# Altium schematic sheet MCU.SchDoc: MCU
size A4; Date: Not used; ApprovedBy: Not used; CheckedBy: Not used; Author: Not used; CompanyName: STMicroelectronics; DrawnBy: Not used; Engineer: Not used; Organization: Not used; Address1: Not used; Address2: Not used; Address3: Not used; Address4: Not used; DocumentNumber: Not used; Revision: Not used; SheetNumber: 3; SheetTotal: 6
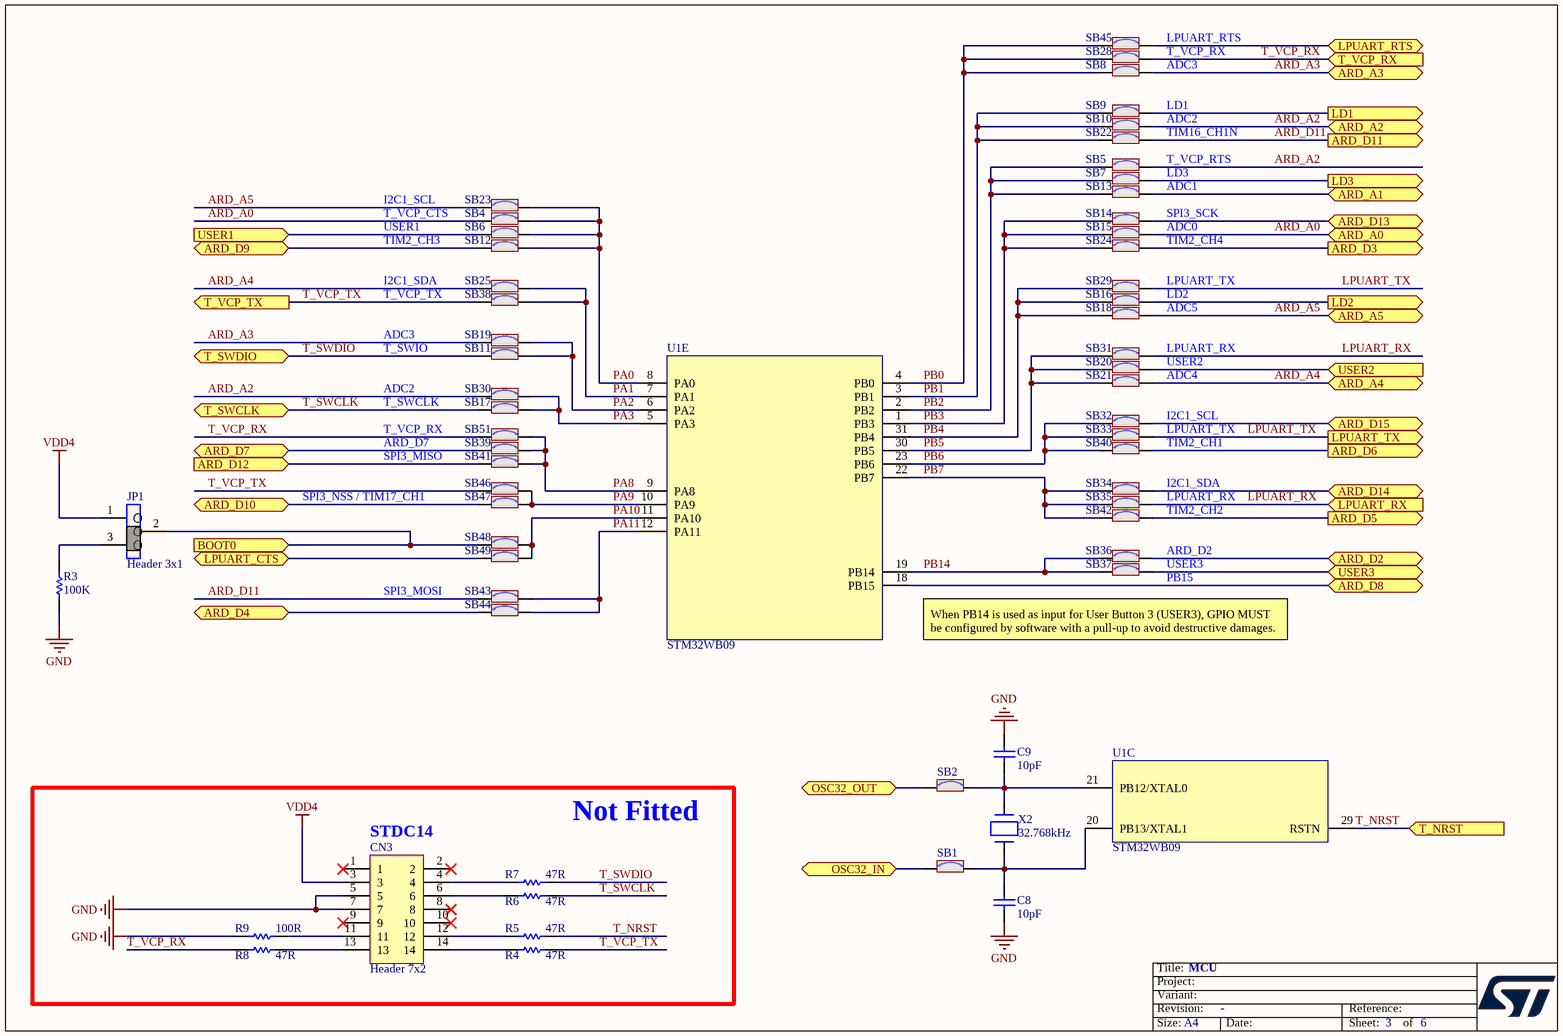
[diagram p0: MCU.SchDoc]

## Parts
C8  value 10pF  [C0402]  (hidden comment: Capacitor)
C9  value 10pF  [C0402]  (hidden comment: Capacitor)
CN3  Header 7x2  [CON_SAMTEC_FTSH-107-01-L-DV-K]
JP1  value Header 3x1  [CON_SAMTEC_TSW-103-07-F-S]  (hidden comment: Jumper_Header 3x1 Fitted 2-3)
R3  value 100K  [R0402]  (hidden comment: Resistor)
R4  value 47R  [R0402]  (hidden comment: Resistor)
R5  value 47R  [R0402]  (hidden comment: Resistor)
R6  value 47R  [R0402]  (hidden comment: Resistor)
R7  value 47R  [R0402]  (hidden comment: Resistor)
R8  value 47R  [R0402]  (hidden comment: Resistor)
R9  value 100R  [R0402]  (hidden comment: Resistor)
SB1  SB_ON  [SOLDER-BRIDGE_R0402-0R]  (value not drawn)
SB2  SB_ON  [SOLDER-BRIDGE_R0402-0R]  (value not drawn)
SB4  SB_ON  [SOLDER-BRIDGE_R0402-0R]  (value not drawn)
SB5  SB_ON  [SOLDER-BRIDGE_R0402-0R]  (value not drawn)
SB6  SB_ON  [SOLDER-BRIDGE_R0402-0R]  (value not drawn)
SB7  SB_ON  [SOLDER-BRIDGE_R0402-0R]  (value not drawn)
SB8  SB_ON  [SOLDER-BRIDGE_R0402-0R]  (value not drawn)
SB9  SB_ON  [SOLDER-BRIDGE_R0402-0R]  (value not drawn)
SB10  SB_ON  [SOLDER-BRIDGE_R0402-0R]  (value not drawn)
SB11  SB_ON  [SOLDER-BRIDGE_R0402-0R]  (value not drawn)
SB12  SB_ON  [SOLDER-BRIDGE_R0402-0R]  (value not drawn)
SB13  SB_ON  [SOLDER-BRIDGE_R0402-0R]  (value not drawn)
SB14  SB_ON  [SOLDER-BRIDGE_R0402-0R]  (value not drawn)
SB15  SB_ON  [SOLDER-BRIDGE_R0402-0R]  (value not drawn)
SB16  SB_ON  [SOLDER-BRIDGE_R0402-0R]  (value not drawn)
SB17  SB_ON  [SOLDER-BRIDGE_R0402-0R]  (value not drawn)
SB18  SB_ON  [SOLDER-BRIDGE_R0402-0R]  (value not drawn)
SB19  SB_ON  [SOLDER-BRIDGE_R0402-0R]  (value not drawn)
SB20  SB_ON  [SOLDER-BRIDGE_R0402-0R]  (value not drawn)
SB21  SB_ON  [SOLDER-BRIDGE_R0402-0R]  (value not drawn)
SB22  SB_ON  [SOLDER-BRIDGE_R0402-0R]  (value not drawn)
SB23  SB_ON  [SOLDER-BRIDGE_R0402-0R]  (value not drawn)
SB24  SB_ON  [SOLDER-BRIDGE_R0402-0R]  (value not drawn)
SB25  SB_ON  [SOLDER-BRIDGE_R0402-0R]  (value not drawn)
SB28  SB_ON  [SOLDER-BRIDGE_R0402-0R]  (value not drawn)
SB29  SB_ON  [SOLDER-BRIDGE_R0402-0R]  (value not drawn)
SB30  SB_ON  [SOLDER-BRIDGE_R0402-0R]  (value not drawn)
SB31  SB_ON  [SOLDER-BRIDGE_R0402-0R]  (value not drawn)
SB32  SB_ON  [SOLDER-BRIDGE_R0402-0R]  (value not drawn)
SB33  SB_ON  [SOLDER-BRIDGE_R0402-0R]  (value not drawn)
SB34  SB_ON  [SOLDER-BRIDGE_R0402-0R]  (value not drawn)
SB35  SB_ON  [SOLDER-BRIDGE_R0402-0R]  (value not drawn)
SB36  SB_ON  [SOLDER-BRIDGE_R0402-0R]  (value not drawn)
SB37  SB_ON  [SOLDER-BRIDGE_R0402-0R]  (value not drawn)
SB38  SB_ON  [SOLDER-BRIDGE_R0402-0R]  (value not drawn)
SB39  SB_ON  [SOLDER-BRIDGE_R0402-0R]  (value not drawn)
SB40  SB_ON  [SOLDER-BRIDGE_R0402-0R]  (value not drawn)
SB41  SB_ON  [SOLDER-BRIDGE_R0402-0R]  (value not drawn)
SB42  SB_ON  [SOLDER-BRIDGE_R0402-0R]  (value not drawn)
SB43  SB_ON  [SOLDER-BRIDGE_R0402-0R]  (value not drawn)
SB44  SB_ON  [SOLDER-BRIDGE_R0402-0R]  (value not drawn)
SB45  SB_ON  [SOLDER-BRIDGE_R0402-0R]  (value not drawn)
SB46  SB_ON  [SOLDER-BRIDGE_R0402-0R]  (value not drawn)
SB47  SB_ON  [SOLDER-BRIDGE_R0402-0R]  (value not drawn)
SB48  SB_ON  [SOLDER-BRIDGE_R0402-0R]  (value not drawn)
SB49  SB_ON  [SOLDER-BRIDGE_R0402-0R]  (value not drawn)
SB51  SB_ON  [SOLDER-BRIDGE_R0402-0R]  (value not drawn)
U1  STM32WB09  [ICC_QFN32-EPAD_5X5_P050]  (parts C,E of 5)
X2  value 32.768kHz  [CRY_NX2012SA_2P]  (hidden comment: XTAL_2_PINS)

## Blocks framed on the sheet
Not Fitted: CN3 R4-R9

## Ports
ARD_A0 (bidir), ARD_A1 (bidir), ARD_A2 (bidir), ARD_A3 (bidir), ARD_A4 (bidir), ARD_A5 (bidir), ARD_D2 (bidir), ARD_D3 (out), ARD_D4 (bidir), ARD_D5 (out), ARD_D6 (out), ARD_D7 (bidir), ARD_D8 (bidir), ARD_D9 (bidir), ARD_D10 (bidir), ARD_D11 (out), ARD_D12 (in), ARD_D13 (bidir), ARD_D14 (bidir), ARD_D15 (bidir), BOOT0 (in), LD1 (out), LD2 (out), LD3 (out), LPUART_CTS (bidir), LPUART_RTS (bidir), LPUART_RX (in), LPUART_TX (out), OSC32_IN (bidir), OSC32_OUT (bidir), T_NRST (in), T_SWCLK (bidir), T_SWDIO (bidir), T_VCP_RX (in), T_VCP_TX (out), USER1 (in), USER2 (in), USER3 (bidir)

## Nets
GND: C8.1 C9.2 CN3.5 CN3.7 R3.1 R9.1
VDD4: CN3.3 JP1.1
ARD_A0: SB4.1 SB15.2 ; port ARD_A0
ARD_A1: SB13.2 ; port ARD_A1
ARD_A2: SB5.2 SB10.2 SB30.1 ; port ARD_A2
ARD_A3: SB8.2 SB19.1 ; port ARD_A3
ARD_A4: SB21.2 SB25.1 ; port ARD_A4
ARD_A5: SB18.2 SB23.1 ; port ARD_A5
ARD_D2: SB36.2 ; port ARD_D2
ARD_D3: SB24.2 ; port ARD_D3
ARD_D4: SB44.1 ; port ARD_D4
ARD_D5: SB42.2 ; port ARD_D5
ARD_D6: SB40.2 ; port ARD_D6
ARD_D7: SB39.1 ; port ARD_D7
ARD_D8: U1.18(PB15) ; port ARD_D8
ARD_D9: SB12.1 ; port ARD_D9
ARD_D10: SB47.1 ; port ARD_D10
ARD_D11: SB22.2 SB43.1 ; port ARD_D11
ARD_D12: SB41.1 ; port ARD_D12
ARD_D13: SB14.2 ; port ARD_D13
ARD_D14: SB34.2 ; port ARD_D14
ARD_D15: SB32.2 ; port ARD_D15
BOOT0: JP1.2 SB48.1 ; port BOOT0
LD1: SB9.2 ; port LD1
LD2: SB16.2 ; port LD2
LD3: SB7.2 ; port LD3
LPUART_CTS: SB49.1 ; port LPUART_CTS
LPUART_RTS: SB45.2 ; port LPUART_RTS
LPUART_RX: SB31.2 SB35.2 ; port LPUART_RX
LPUART_TX: SB29.2 SB33.2 ; port LPUART_TX
OSC32_IN: SB1.1 ; port OSC32_IN
OSC32_OUT: SB2.1 ; port OSC32_OUT
PA0: SB4.2 SB6.2 SB12.2 SB23.2 U1.8(PA0)
PA1: SB25.2 SB38.2 U1.7(PA1)
PA2: SB11.2 SB19.2 U1.6(PA2)
PA3: SB17.2 SB30.2 U1.5(PA3)
PA8: SB39.2 SB41.2 SB51.1 U1.9(PA8)
PA9: SB46.2 SB47.2 U1.10(PA9)
PA10: SB48.2 SB49.2 U1.11(PA10)
PA11: SB43.2 SB44.2 U1.12(PA11)
PB0: SB8.1 SB28.1 SB45.1 U1.4(PB0)
PB1: SB9.1 SB10.1 SB22.1 U1.3(PB1)
PB2: SB5.1 SB7.1 SB13.1 U1.2(PB2)
PB3: SB14.1 SB15.1 SB24.1 U1.1(PB3)
PB4: SB16.1 SB18.1 SB29.1 U1.31(PB4)
PB5: SB20.1 SB21.1 SB31.1 U1.30(PB5)
PB6: SB32.1 SB33.1 SB40.1 U1.23(PB6)
PB7: SB34.1 SB35.1 SB42.1 U1.22(PB7)
PB14: SB36.1 SB37.1 U1.19(PB14)
T_NRST: R5.2 U1.29(RSTN) ; port T_NRST
T_SWCLK: R6.2 SB17.1 ; port T_SWCLK
T_SWDIO: R7.2 SB11.1 ; port T_SWDIO
T_VCP_RX: R8.1 SB28.2 SB51.2 ; port T_VCP_RX
T_VCP_TX: R4.2 SB38.1 SB46.1 ; port T_VCP_TX
USER1: SB6.1 ; port USER1
USER2: SB20.2 ; port USER2
USER3: SB37.2 ; port USER3
NetC8_2: C8.2 SB1.2 U1.20(PB13/XTAL1) X2.2(X2)
NetC9_1: C9.1 SB2.2 U1.21(PB12/XTAL0) X2.1(X1)
NetCN3_4: CN3.4 R7.1
NetCN3_6: CN3.6 R6.1
NetCN3_11: CN3.11 R9.2
NetCN3_12: CN3.12 R5.1
NetCN3_13: CN3.13 R8.2
NetCN3_14: CN3.14 R4.1
NetJP1_3: JP1.3 R3.2

Not connected (* = marked no-connect by the designer): CN3 1* 2* 8* 9* 10*

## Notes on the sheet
- LPUART_RTS
- ADC3
- T_VCP_RX
- LD1
- ADC2
- LD3
- TIM16_CH1N
- T_VCP_RTS
- TIM2_CH3
- T_VCP_CTS
- I2C1_SCL
- USER1
- ADC0
- ADC1
- TIM2_CH4
- SPI3_SCK
- I2C1_SDA
- T_VCP_TX
- ADC5
- LD2
- LPUART_TX
- T_SWIO
- ADC4
- LPUART_RX
- USER2
- T_SWCLK
- ARD_D7
- TIM2_CH1
- SPI3_NSS / TIM17_CH1
- SPI3_MISO
- TIM2_CH2
- ARD_D2
- USER3
- PB15
- SPI3_MOSI
- When PB14 is used as input for User Button 3 (USER3), GPIO MUST be configured by software with a pull-up to avoid destructive damages.
- (near CN3) STDC14

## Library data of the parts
C8 C9 = MCD-00015: Capacitor, MLCC, 10pF, 50V, NPO, +/-5%, 0402, T=0.5mm; Part_Preference: Recommended; Manufacturer: YAGEO; Manufacturer_Part_Number: CC0402JRNPO9BN100; Order_Code_RS: 3019160RL; Component_Country_Of_Origin: China; ShowFields: YES; ID: 2465
CN3 = MCD-01531: Header, 7x2, 1.27mm, VR, T=5.97mm, FTSH series STDC14 without Alignment Pin; Part_Type: Connector; Part_Preference: Recommended; Manufacturer: SAMTEC; Manufacturer_Part_Number: FTSH-107-01-L-DV-K; Order_Code_RS: 179-9021; Component_Country_Of_Origin: China, Costa Rica, Malaysia, United States, Vietnam; ShowFields: YES; ID: 3631
JP1 = MCD-00685: Header, 3x1, 2.54mm, VR, TH, T=5.84mm/2.54mm; Part_Type: Connector; Part_Preference: Recommended; Manufacturer: SAMTEC; Manufacturer_Part_Number: TSW-103-07-F-S; Order_Code_RS: 161-2248; Component_Country_Of_Origin: China, Costa Rica, Malaysia, United States, Vietnam; ShowFields: YES; ID: 3058
R3 = MCD-00059: Resistor, 100K, 0402, +/-1%, 1/16W; Part_Preference: Recommended; Manufacturer: YAGEO; Manufacturer_Part_Number: RC0402FR-07100KL; Partial_Alternate_Internal_Part_Number: MCD-03301; Order_Code_RS: 2421891; Component_Country_Of_Origin: China; ShowFields: YES; ID: 2533
R4-R8 = MCD-00481: Resistor, 47R, 0402, +/-1%, 1/16W; Part_Preference: Recommended; Manufacturer: YAGEO; Manufacturer_Part_Number: RC0402FR-0747RL; Component_Country_Of_Origin: China; ShowFields: YES; ID: 2796
R9 = MCD-00067: Resistor, 100R, 0402, +/- 1%, 1/16W; Part_Preference: Recommended; Manufacturer: YAGEO; Manufacturer_Part_Number: RC0402FR-07100RL; Order_Code_RS: 9239111; Component_Country_Of_Origin: China; ShowFields: YES; ID: 2527
SB1 SB2 SB4-SB25 SB28-SB49 SB51 = MCD-01618: Solder Bridge 0402 ON; Part_Type: Resistor; Part_Preference: Recommended; Manufacturer: YAGEO; Manufacturer_Part_Number: RC0402JR-070RL; Value: 0R; Order_Code_RS: 618-5804; Component_Country_Of_Origin: China; ShowFields: YES; ID: 3718
U1 = MCD-03444: Bluetooth® Low Energy wireless SoC; Part_Type: IC; Part_Preference: Recommended; Manufacturer: STMICROELECTRONICS; Component_Country_Of_Origin: Unknown; ShowFields: YES; ID: 5560
X2 = MCD-01445: Crystal, 32.768kHz, 7pF, +/-20ppm, 80K, 2.05x1.2mm; BMS_Part_Number: 9157043; Part_Type: Crystal_Osc; Part_Preference: Recommended; Manufacturer: NDK; Manufacturer_Part_Number: NX2012SA-32.768KHZ-EXS00A-MU00389; Component_Country_Of_Origin: Unknown; ShowFields: YES; ID: 3545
